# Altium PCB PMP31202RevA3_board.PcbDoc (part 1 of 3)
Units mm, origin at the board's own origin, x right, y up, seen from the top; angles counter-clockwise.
Board outline 156.21 x 130.81 mm, 4 copper layers (Top Layer, Layer 2, Layer 3, Bottom Layer), stack 1.671 mm thick; 198 components, 74 nets, 489 pads, 691 vias.
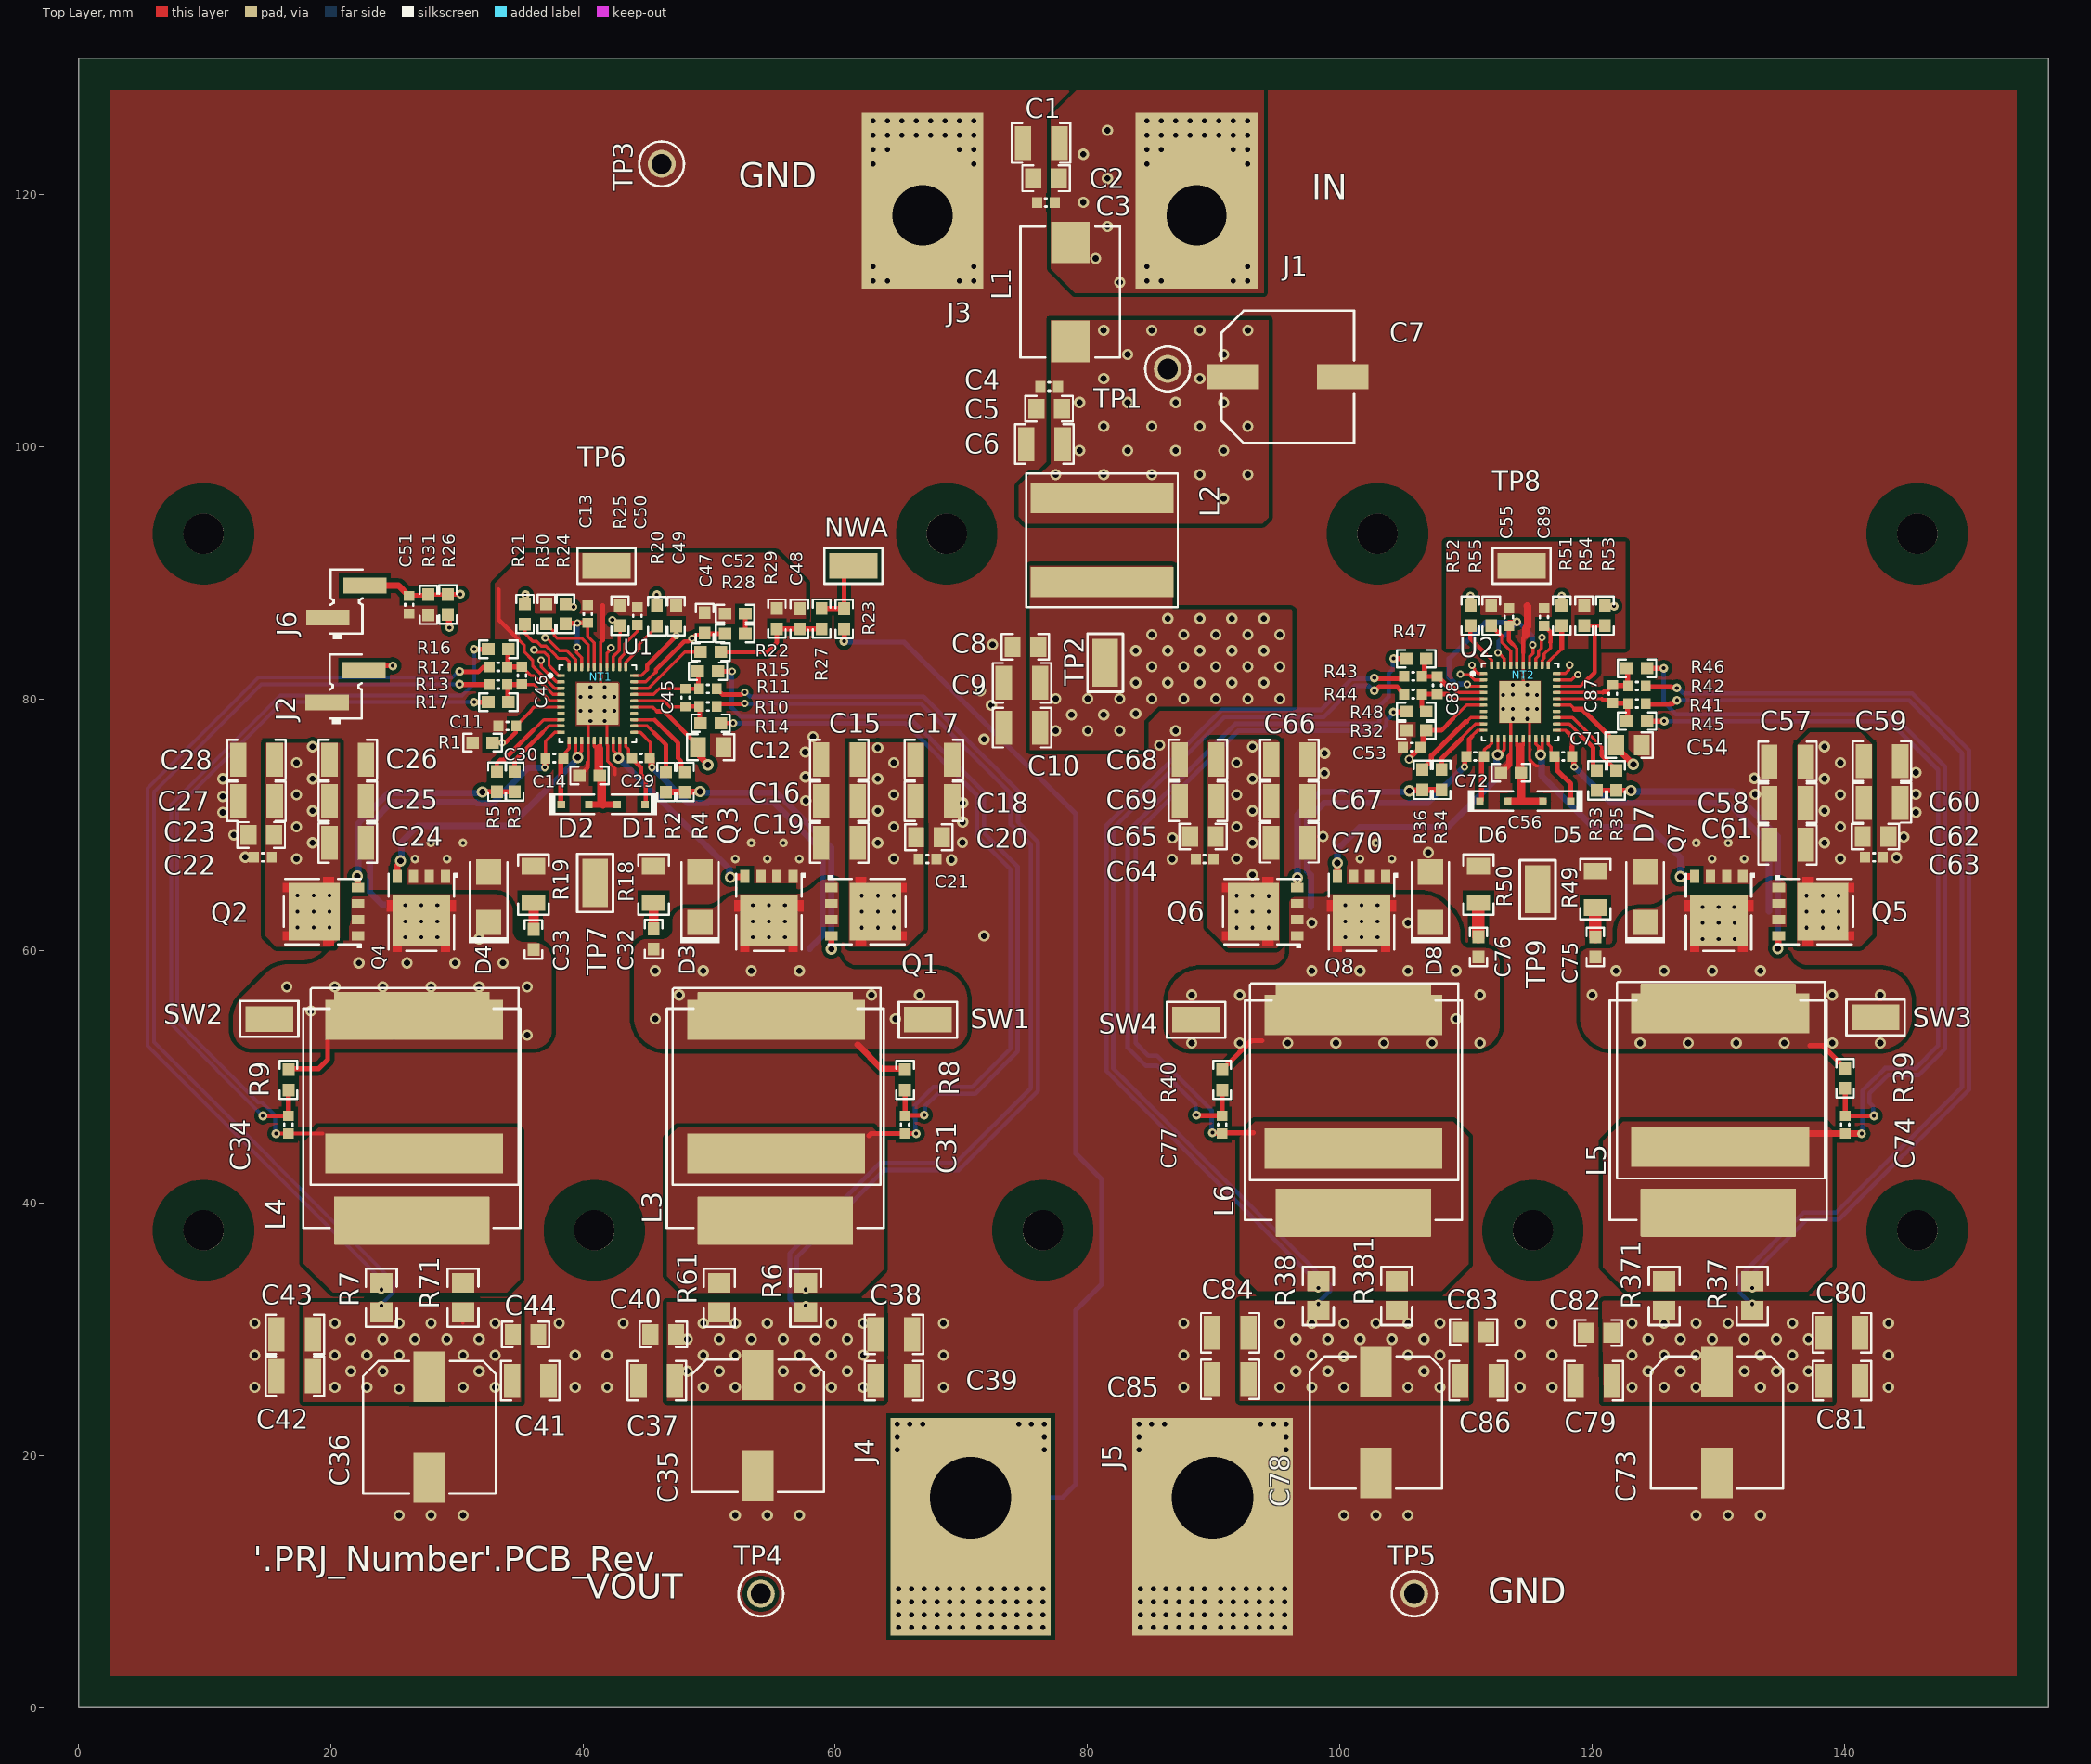
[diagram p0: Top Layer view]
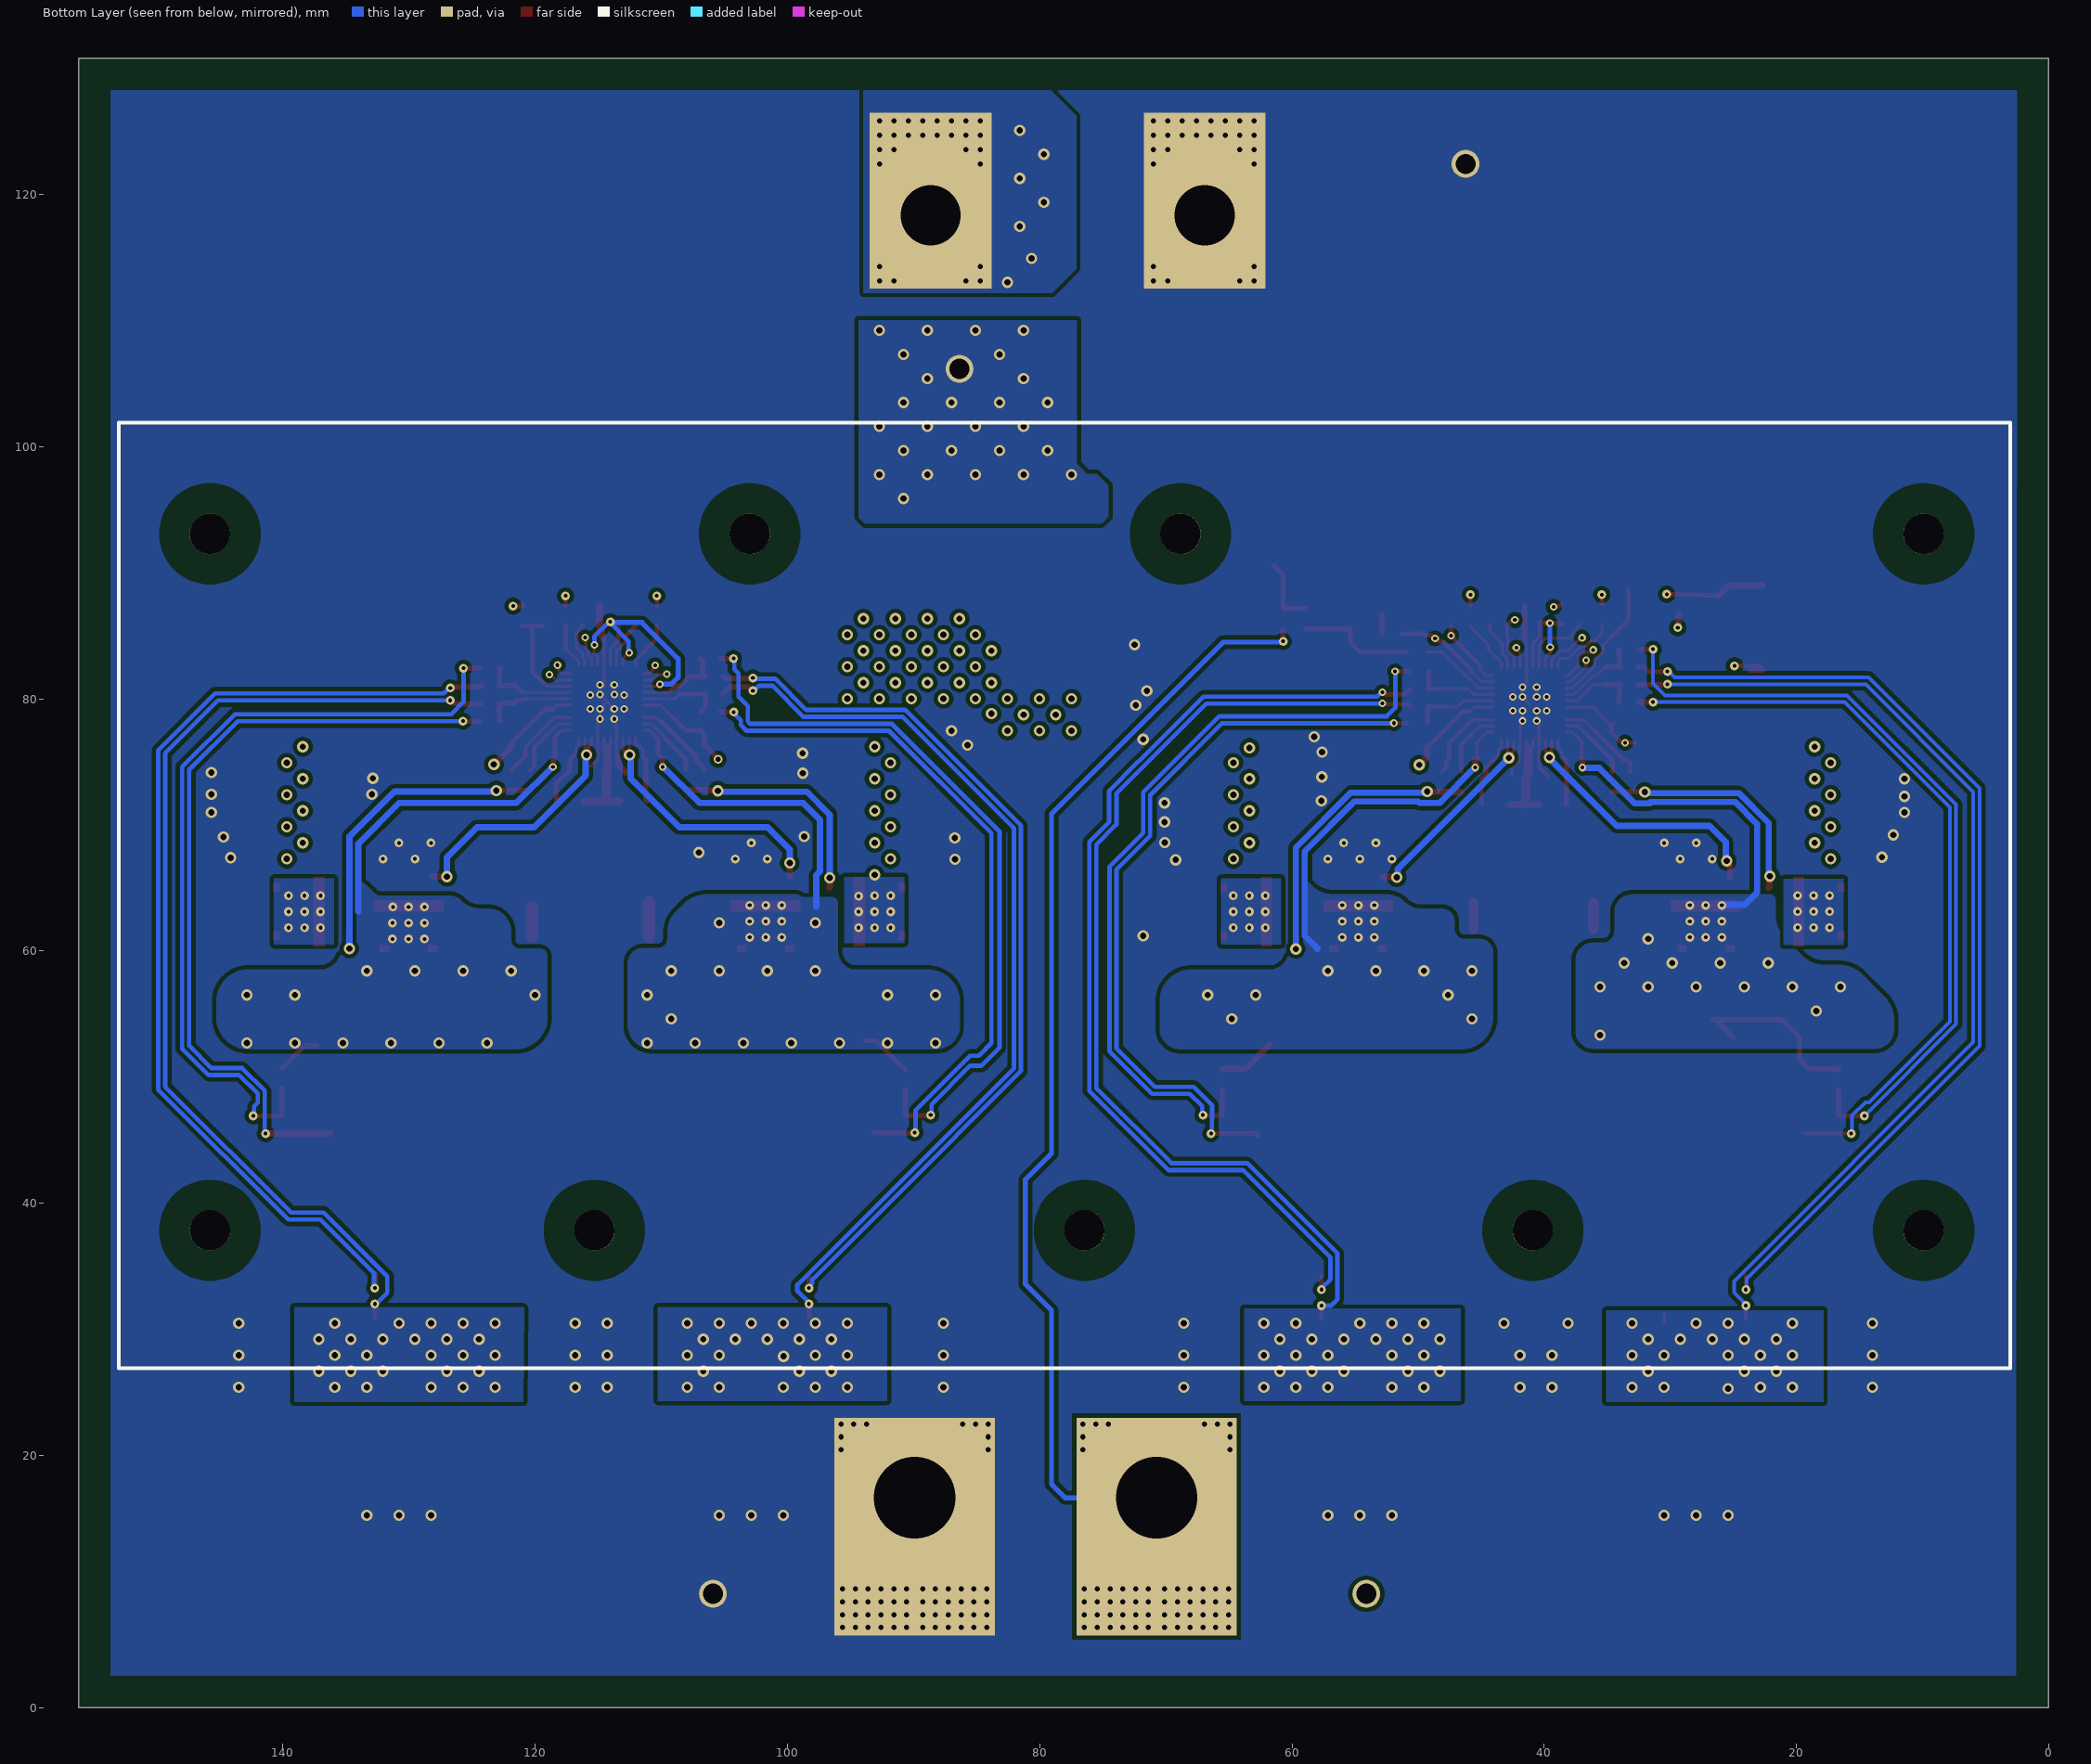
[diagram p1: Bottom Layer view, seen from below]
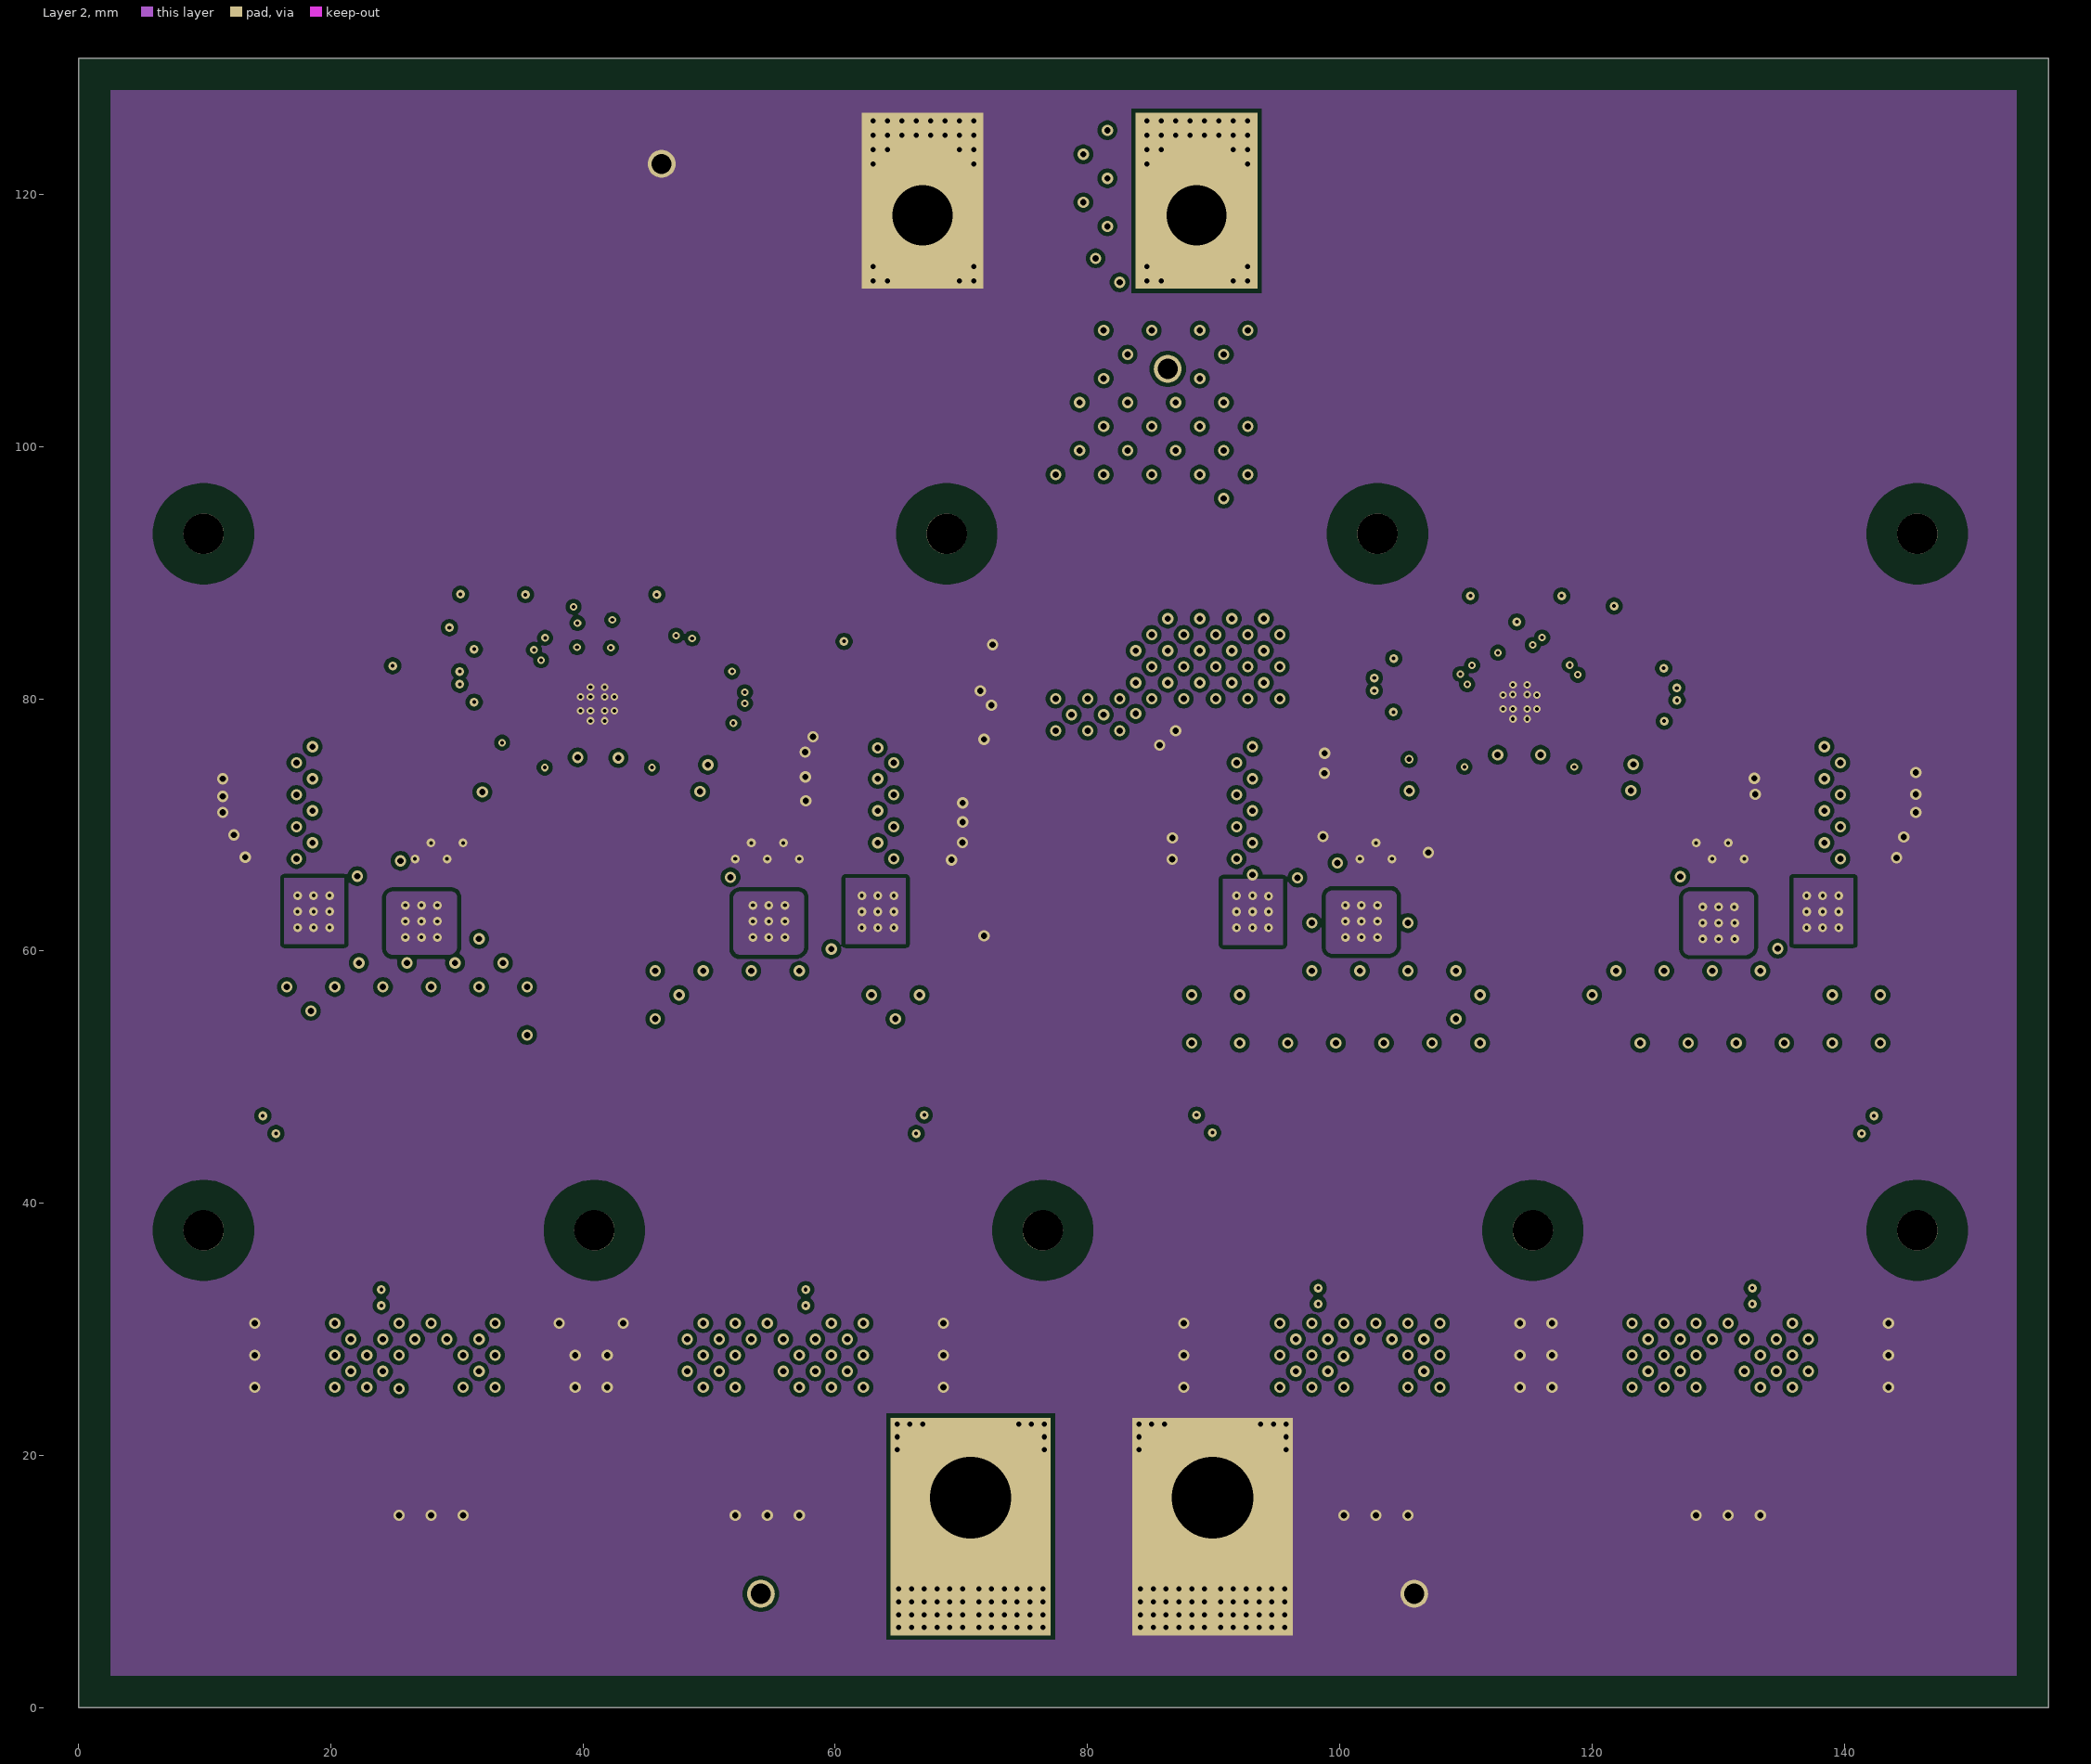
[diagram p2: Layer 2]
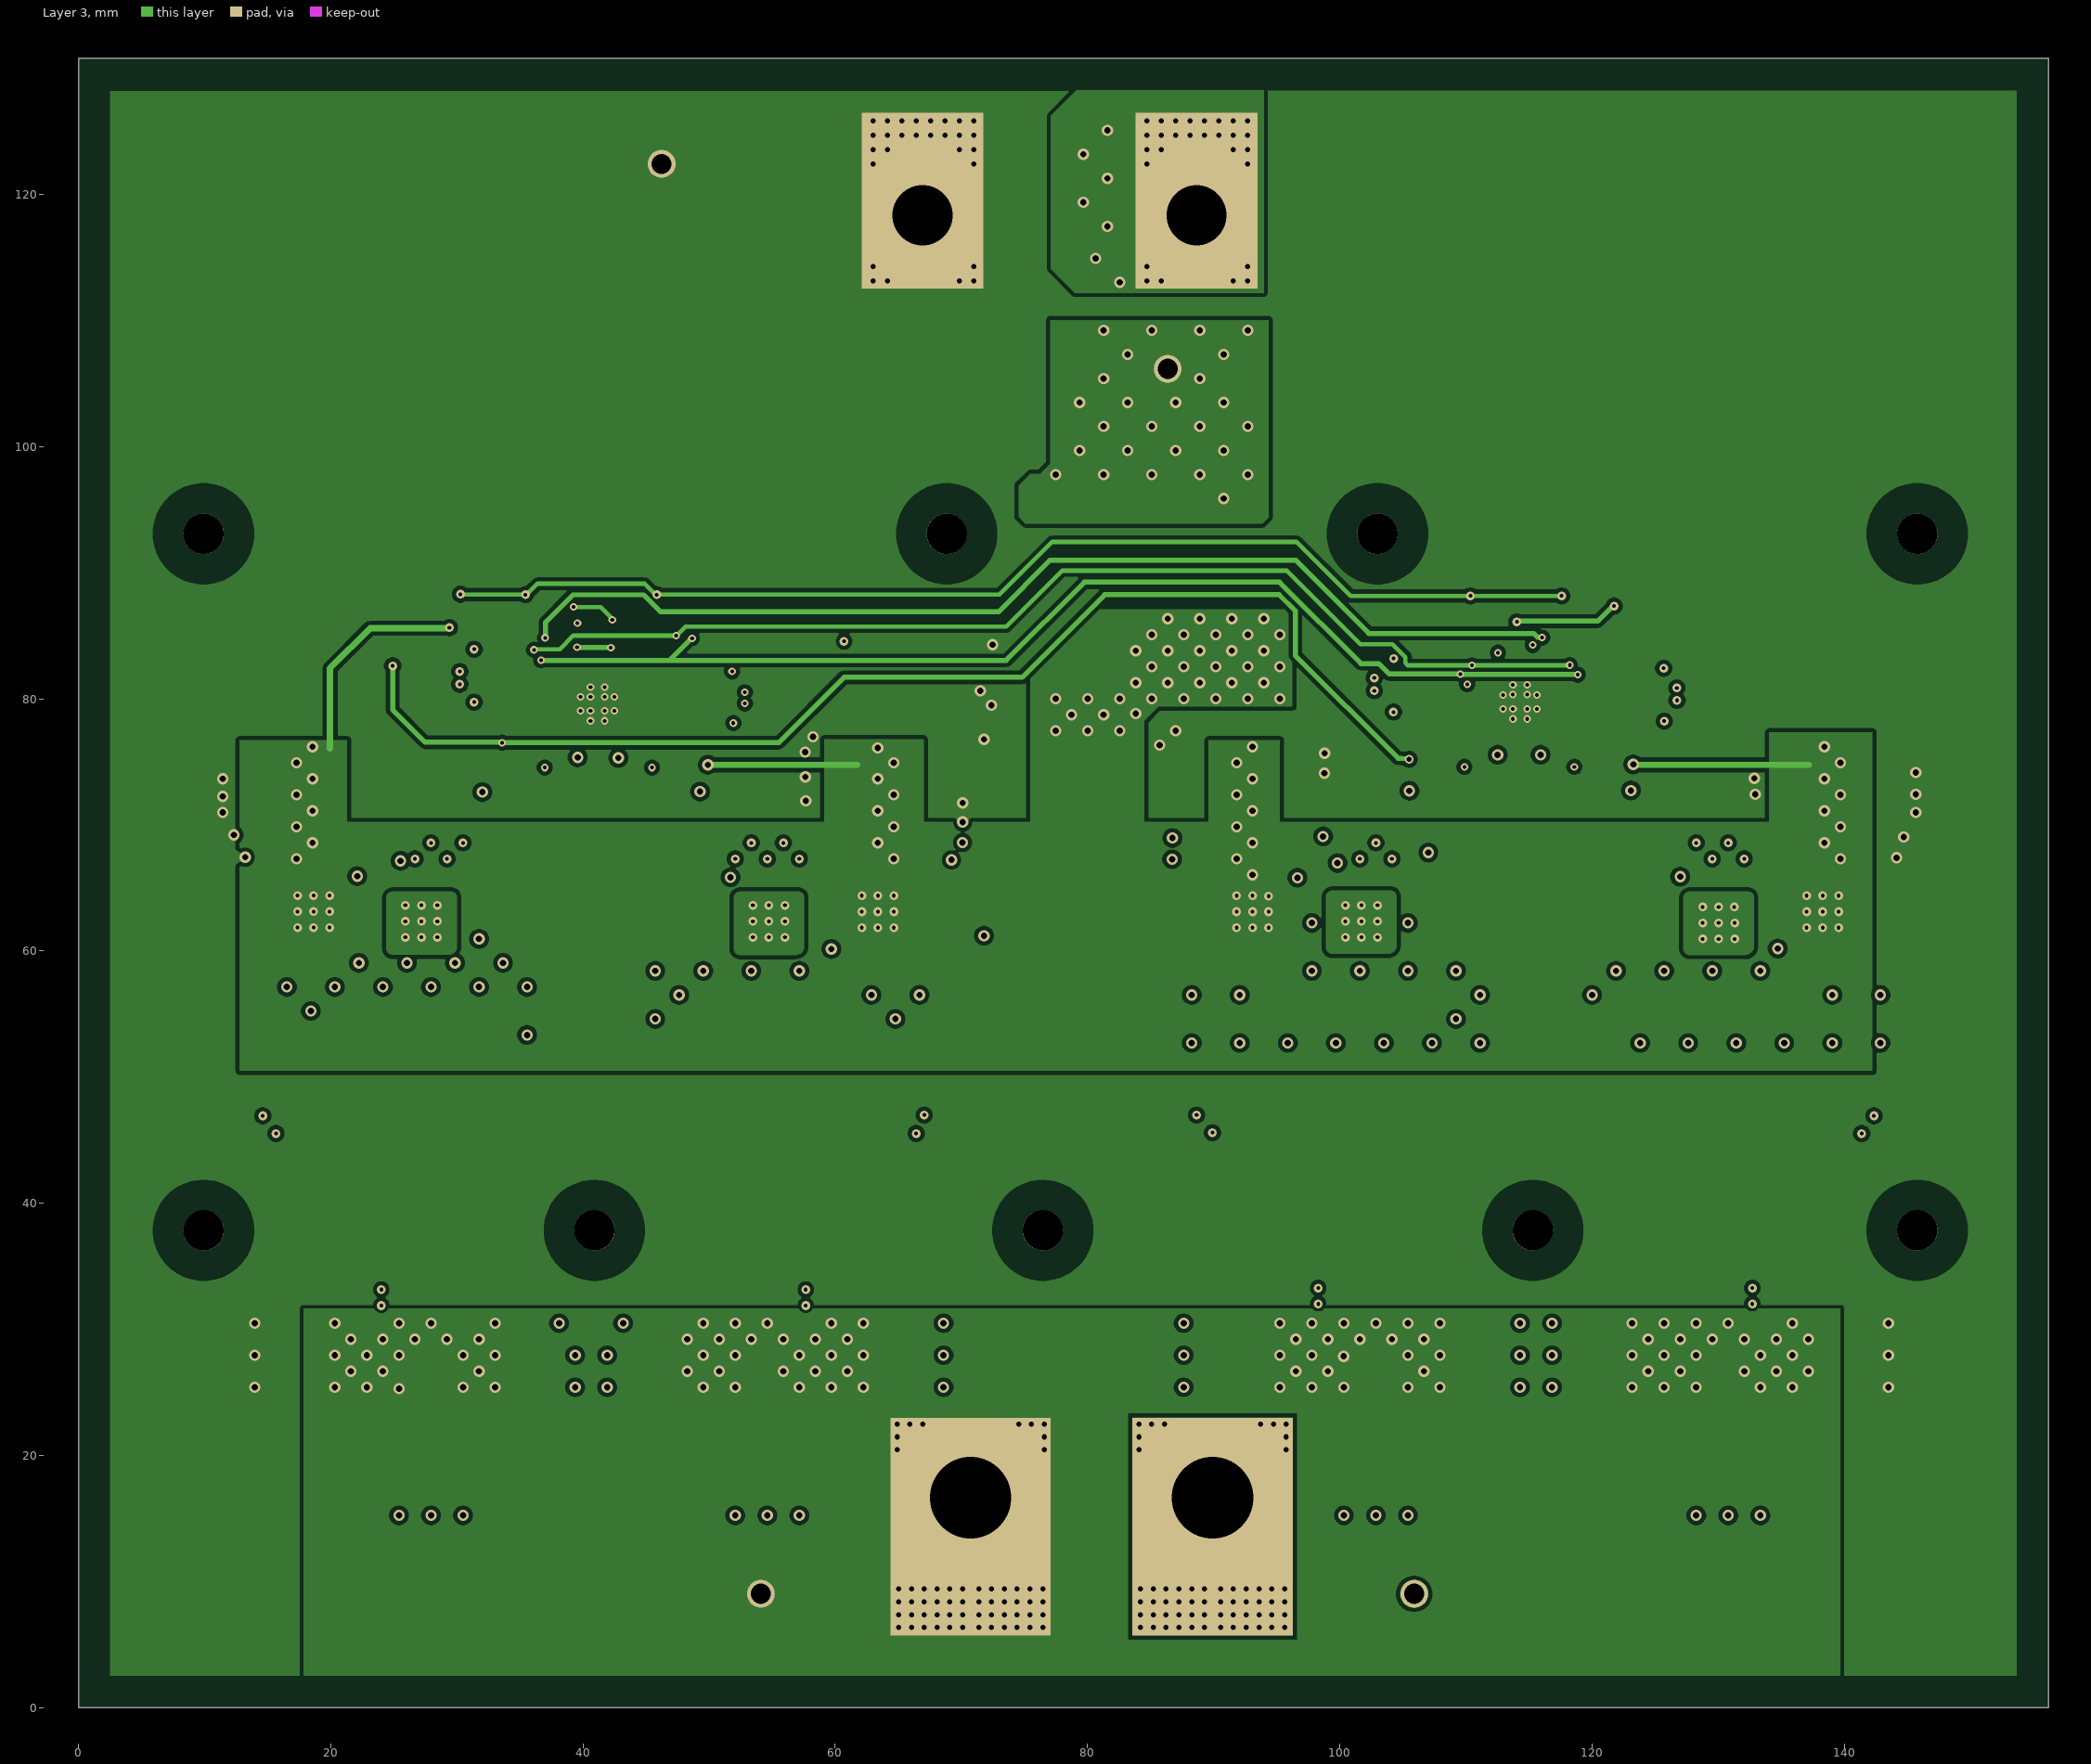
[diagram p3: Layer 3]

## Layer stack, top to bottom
Top Solder: solder mask 0.0102, Solder Resist, Dk 3.5
Top Layer: signal copper 0.0356
Dielectric 2: prepreg 0.41, PP-006, Dk 4.1
Layer 2: signal copper 0.035
Dielectric3: prepreg 0.71, FR-4, Dk 4.8
Layer 3: signal copper 0.035
Dielectric 3: prepreg 0.41, PP-006, Dk 4.1
Bottom Layer: signal copper 0.0356
Bottom Solder: solder mask 0.0102, Solder Resist, Dk 3.5

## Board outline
0,0 156.21,0 156.21,130.81 0,130.81

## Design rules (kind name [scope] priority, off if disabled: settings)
AcuteAngle [All] p1: minimum=4.50000000000000E+0001 checktracksonly=FALSE
AssemblyTestPointUsage [All] p1: valid=2
BoardOutlineClearance BoardOutlineClearance_MountingHoles [OnCopper and InComponentClass('Mounting Holes')] p1: gap=1 ignorepadtopadclearanceinfootprint=FALSE
BoardOutlineClearance BoardOutlineClearance_Poly [OnCopper and IsPoly] p2: gap=0.635 ignorepadtopadclearanceinfootprint=FALSE
BoardOutlineClearance [OnCopper and Not InComponentClass('Logo') and not InComponentClass('FiducialMark') and not InRegion(1000,500,4000,800) and not InPoly] p3: gap=1.905 ignorepadtopadclearanceinfootprint=FALSE
Clearance Clearance_Keepouts [((IsTrack Or IsArc) And Not InPoly) And IsFree and IsKeepOut vs ((IsTrack Or IsArc) And Not InPoly) And IsFree and IsKeepOut] p1: gap=0 ignorepadtopadclearanceinfootprint=FALSE
Clearance Clearance_Screws [All vs HasPad('Free-*')] p2: gap=2.4 ignorepadtopadclearanceinfootprint=TRUE
Clearance Clearance_Poly [InPolygon] p3: gap=0.32 ignorepadtopadclearanceinfootprint=TRUE
Clearance Clearance_FiducialMark [IsKeepOut and InComponentClass('FiducialMark') vs IsPad and InComponentClass('FiducialMark')] p4: gap=0 ignorepadtopadclearanceinfootprint=FALSE
Clearance [All] p5: gap=0.2 ignorepadtopadclearanceinfootprint=TRUE
ComponentClearance ComponentClearance_MountingHoles_FiducialMarks [InComponentClass('Mounting Holes') vs InComponentClass('FiducialMark')] p1: gap=1.27 collisioncheckmode=3 verticalgap=0.254 showdistances=FALSE
ComponentClearance ComponentClearance_Shunt [InComponentClass('Header') vs InComponentClass('Shunt')] p2: gap=0 collisioncheckmode=3 verticalgap=0 showdistances=FALSE
ComponentClearance ComponentClearance_Logo [InComponentClass('Logo')] p3: gap=1.27 collisioncheckmode=3 verticalgap=0.254 showdistances=FALSE
ComponentClearance ComponentClearance_ScrewToNut [(HasFootprint('NY PMS 440 0025 PH')) vs (HasFootprint('Keystone_1902C'))] p4: gap=0.127 collisioncheckmode=3 verticalgap=0.254 showdistances=FALSE
ComponentClearance ComponentClearance_MountingHoles [InComponentClass('Mounting Holes')] p5: gap=6.35 collisioncheckmode=3 verticalgap=2540 showdistances=FALSE
ComponentClearance ComponentClearance_Net_Tie [HasFootprint('Net-Tie_10mil') vs HasFootprint('RHA0040N-MFG')] p6: gap=0 collisioncheckmode=3 verticalgap=0 showdistances=FALSE
ComponentClearance ComponentClearance_SmallPassives [HasFootprint('0201*') or HasFootprint('0402*') or HasFootprint('0508') or HasFootprint('0603*') or HasFootprint('0612') or HasFootprint('0805*') or HasFootprint('0815*') or HasFootprint('0830*') or HasFootprint('1206*') or HasFootprint('1210*') or HasFootprint('1808*') or HasFootprint('1812*') or HasFootprint('1825*') or HasFootprint('2010*') or HasFootprint('2220*') or HasFootprint('2225*') or HasFootprint('2512*') or HasFootprint('2728*') or HasFootprint('3518*') vs HasFootprint('0201*') or HasFootprint('0402*') or HasFootprint('0508') or HasFootprint('0603*') or HasFootprint('0612') or HasFootprint('0805*') or HasFootprint('0815*') or HasFootprint('0830*') or HasFootprint('1206*') or HasFootprint('1210*') or HasFootprint('1808*') or HasFootprint('1812*') or HasFootprint('1825*') or HasFootprint('2010*') or HasFootprint('2220*') or HasFootprint('2225*') or HasFootprint('2512*') or HasFootprint('2728*') or HasFootprint('3518*')] p7: gap=0.38 collisioncheckmode=3 verticalgap=0.254 showdistances=FALSE
ComponentClearance ComponentClearance_THtoSMT [IsThruComponent vs IsSMTComponent] p8: gap=1.016 collisioncheckmode=3 verticalgap=0.762 showdistances=FALSE
ComponentClearance ComponentClearance_THtoTH [IsThruComponent vs IsThruComponent] p9: gap=0.762 collisioncheckmode=3 verticalgap=0.762 showdistances=FALSE
ComponentClearance [All] p10: gap=0.762 collisioncheckmode=3 verticalgap=0.254 showdistances=FALSE
DiffPairsRouting [All] p1: maxlimit=2.54 minlimit=0.254 mostfreqgap=0.254 toplayer_minwidth=0.381 toplayer_maxwidth=0.381 toplayer_prefwidth=0.381 midlayer1_minwidth=0.381 midlayer1_maxwidth=0.381 midlayer1_prefwidth=0.381 midlayer2_minwidth=0.381 midlayer2_maxwidth=0.381 midlayer2_prefwidth=0.381 bottomlayer_minwidth=0.381 bottomlayer_maxwidth=0.381 bottomlayer_prefwidth=0.381 maxuncoupledlength=25.4
FabricationTestPointUsage TestPointUsage [All] p1: valid=2 allowmultiple=FALSE
FabricationTestpoint Testpoint [All] p1: side=3 testpointundercomponent=TRUE minsize=1.016 maxsize=2.54 preferedsize=1.524 minholesize=0 maxholesize=1.016 preferedholesize=0.813 testpointgrid=0.025 allowsidetop=TRUE allowsidebottom=TRUE usegrid=TRUE gridtolerance=0
FanoutControl Fanout_LCC [IsLCC] p1: bgadir=Out bgaviamode=Centered fanoutstyle=Auto fanoutdirection=Alternating viagrid=0.025 // Fanout_LCC (Default Rule)
FanoutControl Fanout_BGA [IsBGA] p2: bgadir=Out bgaviamode=Centered fanoutstyle=Auto fanoutdirection=Alternating viagrid=0.025 // Fanout_BGA (Default Rule)
FanoutControl Fanout_Default [All] p4: bgadir=Out bgaviamode=Centered fanoutstyle=Auto fanoutdirection=Alternating viagrid=0.025 // Fanout_Default (Default Rule)
FanoutControl Fanout_Small [(CompPinCount < 5)] p5: bgadir=Out bgaviamode=Centered fanoutstyle=Auto fanoutdirection=OutThenIn viagrid=0.025 // Fanout_Small (Default Rule)
HoleSize [All] p1: absolutevalues=TRUE maxlimit=6.5 minlimit=0.3 maxpercent=80.000 minpercent=20.000
MinimumAnnularRing MinimumAnnularRing_ThermalPadVias [IsVia and InAnyComponent] p1: minimumring=0.15
MinimumAnnularRing [All] p2: minimumring=0.15
MinimumSolderMaskSliver MinimumSolderMaskSliver_Logo [InComponentClass('Logo') vs InComponentClass('Logo')] p1: minsoldermaskwidth=0.018
MinimumSolderMaskSliver [All] p2: minsoldermaskwidth=0.1
PlaneConnect [All] p1: planeconnectstyle=Relief reliefexpansion=0.254 reliefentries=4 reliefconductorwidth=0.254 reliefairgap=0.254
PolygonConnect [All] p1: connectstyle=Direct reliefconductorwidth=0.254 reliefentries=4 polygonreliefangle="90 Angle" airgapwidth=0.254
RoutingLayers [All] p1: top layer_v5=TRUE mid layer 1_v5=FALSE mid layer 2_v5=TRUE bottom layer_v5=TRUE
RoutingVias ThermalPadVias [IsVia and InAnyComponent] p1: holewidth=0.2 width=0.5 viastyle="Through Hole" minholewidth=0.2 minwidth=0.5 maxholewidth=0.5 maxwidth=0.9
RoutingVias [All] p2: holewidth=0.5 width=0.9 viastyle="Through Hole" minholewidth=0.3 minwidth=0.6 maxholewidth=1.016 maxwidth=1.651
SilkToBoardRegionClearance [Not ((IsComment or IsDesignator) And (Hide <> 'False')) and not InRegion(1000,500,4000,800)] p1:
SilkToSilkClearance SilkToSilkClearance_Pb-FreeLogo [(HasFootprint('Pb-Free_Overlay_Medium') OR HasFootprint('Pb-Free_Overlay_Small')) vs (HasFootprint('Pb-Free_Overlay_Medium') OR HasFootprint('Pb-Free_Overlay_Small'))] p1: silktosilkclearance=0
SilkToSilkClearance [All] p2: silktosilkclearance=0.1
SilkToSolderMaskClearance SilkToComponentPadClearance [(IsPad or IsFill or IsRegion) and InAnycomponent] p1: minsilkscreentomaskgap=0.127 clearancetoexposedcopper=TRUE
SilkToSolderMaskClearance "Silk to Solder Mask Opening" [All] p2: minsilkscreentomaskgap=0.1 clearancetoexposedcopper=FALSE
SolderMaskExpansion [All] p1: expansion=0.05 istentingtop=FALSE
UnRoutedNet [All] p1: checkbadconnections=TRUE
Width [All] p1: maxlimit=2.54 minlimit=0.152 preferedwidth=0.254 checkconnectedcopper=TRUE
13 further rules are at their usual default settings.

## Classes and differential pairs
component class PMP31202RevA3-SH2: !PCB1 C53 C54 C55 C56 C57 C58 C59 C60 C61 C62 C63 C64 C65 C66 C67 C68 C69 C70 C71 C72 C73 C74 C75 C76 C77 C78 C79 C80 C81 C82 C83 C84 C85 C86 C87 C88 C89 D5 D6 D7 D8 L5 L6 NT2 Q5 Q6 Q7 Q8 R32 R33 R34 R35 R36 R37 R38 R39 R40 R41 R42 R43 R44 R45 R46 R47 R48 R49 R50 R51 R52 R53 R54 R55 R371 R381 SW3 SW4 TP8 TP9 U2
component class PMP31202RevA3-SH1: C1 C2 C3 C4 C5 C6 C7 C8 C9 C10 C11 C12 C13 C14 C15 C16 C17 C18 C19 C20 C21 C22 C23 C24 C25 C26 C27 C28 C29 C30 C31 C32 C33 C34 C35 C36 C37 C38 C39 C40 C41 C42 C43 C44 C45 C46 C47 C48 C49 C50 C51 C52 D1 D2 D3 D4 J1 J2 J3 J4 J5 J6 L1 L2 L3 L4 NT1 NWA Q1 Q2 Q3 Q4 R1 R2 R3 R4 R5 R6 R7 R8 R9 R10 R11 R12 R13 R14 R15 R16 R17 R18 R19 R20 R21 R22 R23 R24 R25 R26 R27 R28 R29 R30 R31 R61 R71 SW1 SW2 TP1 TP2 TP3 TP4 TP5 TP6 TP7 U1
component class Header: J2 J6

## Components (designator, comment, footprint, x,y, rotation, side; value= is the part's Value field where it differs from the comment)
C1 "UMJ325KB7106KMHT" 1210_270 76.327,124.079 r180 top value=10uF
C2 "C0805C104K1RACTU" 0805_HV 76.708,121.285 r0 top value=0.1uF
C3 "GRM188R72A103KA01D" 0603L 76.7,119.38 r0 top value=0.01uF
C4 "GRM188R72A103KA01D" 0603L 76.962,104.775 r0 top value=0.01uF
C5 "C0805C104K1RACTU" 0805_HV 76.962,102.997 r0 top value=0.1uF
C6 "UMJ325KB7106KMHT" 1210_270 76.581,100.203 r180 top value=10uF
C7 "EEH-ZC1H101P" Panasonic_G 95.885,105.537 r0 top value=100uF
C8 "C0805C104K1RACTU" 0805_HV 75.081,84.137 r0 top value=0.1uF
C9 "UMJ325KB7106KMHT" 1210_270 74.803,81.272 r180 top value=10uF
C10 "UMJ325KB7106KMHT" 1210_270 74.803,77.716 r180 top value=10uF
C11 "GRM188R71A225KE15D" 0603L 33.998,77.852 r180 top value=2.2uF
C12 "GRM21BR71H105KA12L" 0805_HV 50.118,76.164 r0 top value=1uF
C13 "GCM188R71C474KA55D" 0603L 40.373,86.727 r270 top value=0.47uF
C14 "GRM188Z71C475KE21D" 0603 40.513,73.914 r180 top value=4.7uF
C15 "UMJ325KB7106KMHT" 1210_270 60.325,75.184 r180 top value=10uF
C16 "UMJ325KB7106KMHT" 1210_270 60.325,71.882 r180 top value=10uF
C17 "UMJ325KB7106KMHT" 1210_270 67.818,75.176 r0 top value=10uF
C18 "UMJ325KB7106KMHT" 1210_270 67.818,71.874 r0 top value=10uF
C19 "UMJ325KB7106KMHT" 1210_270 60.325,68.58 r180 top value=10uF
C20 "C0805C104K1RACTU" 0805_HV 67.427,69.025 r180 top value=0.1uF
C21 "GRM188R72A103KA01D" 0603L 67.31,67.31 r180 top value=0.01uF
C22 "GRM188R72A103KA01D" 0603L 14.605,67.429 r0 top value=0.01uF
C23 "C0805C104K1RACTU" 0805_HV 14.478,69.207 r0 top value=0.1uF
C24 "UMJ325KB7106KMHT" 1210_270 21.336,68.572 r0 top value=10uF
C25 "UMJ325KB7106KMHT" 1210_270 21.336,71.874 r0 top value=10uF
C26 "UMJ325KB7106KMHT" 1210_270 21.336,75.176 r0 top value=10uF
C27 "UMJ325KB7106KMHT" 1210_270 14.097,71.874 r180 top value=10uF
C28 "UMJ325KB7106KMHT" 1210_270 14.097,75.176 r180 top value=10uF
C29 "CGA3E2X7R1E104K080AA" 0603L 44.577,75.311 r180 top value=0.1uF
C30 "CGA3E2X7R1E104K080AA" 0603L 37.723,75.297 r0 top value=0.1uF
C31 "CGA3E2X7R1E104K080AA" 0603L 65.532,46.228 r270 top value=0.1uF
C32 "GRM188R71H102KA01D" 0603 45.593,60.96 r90 top value=1000pF
C33 "GRM188R71H102KA01D" 0603 36.068,60.922 r270 top value=1000pF
C34 "CGA3E2X7R1E104K080AA" 0603L 16.637,46.228 r270 top value=0.1uF
C35 "EEHZC1E331P" SM_RADIAL_10BMM 53.848,22.352 r270 top value=330uF
C36 "EEHZC1E331P" SM_RADIAL_10BMM 27.813,22.225 r270 top value=330uF
C37 "GRM32ER71E226KE15L" 1210_270 45.847,25.908 r180 top value=22uF
C38 "GRM32ER71E226KE15L" 1210_270 64.643,29.591 r0 top value=22uF
C39 "GRM32ER71E226KE15L" 1210_270 64.643,25.908 r0 top value=22uF
C40 "C0805C104K1RACTU" 0805_HV 46.355,29.591 r0 top value=0.1uF
C41 "C0805C104K1RACTU" 0805_HV 35.433,29.591 r180 top value=0.1uF
C42 "GRM32ER71E226KE15L" 1210_270 17.137,26.289 r180 top value=22uF
C43 "GRM32ER71E226KE15L" 1210_270 17.137,29.591 r180 top value=22uF
C44 "GRM32ER71E226KE15L" 1210_270 35.814,25.908 r0 top value=22uF
C45 "06031A330JAT2A" 0603L 48.123,80.097 r90 top value=33pF
C46 "06031A330JAT2A" 0603L 35.15,81.846 r90 top value=33pF
C47 "GRM188R71H331KA01D" 0603 49.643,86.024 r90 top value=330pF
C48 "GRM1885C1H100JA01D" 0603 57.154,86.346 r90 top value=10pF
C49 "GRM188R71C334KA01D" 0603 47.375,86.567 r90 top value=0.33uF
C50 "GRM188R71A225KE15D" 0603L 44.302,86.567 r90 top value=2.2uF
C51 "06031A330JAT2A" 0603L 26.209,87.459 r270 top value=33pF
C52 "GRM188R71E153KA01D" 0603 52.06,86.76 r180 top value=0.015uF
C53 "GRM188R71A225KE15D" 0603L 105.715,76.175 r180 top value=2.2uF
C54 "GRM21BR71H105KA12L" 0805_HV 122.936,76.327 r0 top value=1uF
C55 "GCM188R71C474KA55D" 0603L 113.411,86.487 r270 top value=0.47uF
C56 "GRM188Z71C475KE21D" 0603 113.575,74.134 r180 top value=4.7uF
C57 "UMJ325KB7106KMHT" 1210_270 135.509,75.032 r180 top value=10uF
C58 "UMJ325KB7106KMHT" 1210_270 135.509,71.73 r180 top value=10uF
C59 "UMJ325KB7106KMHT" 1210_270 143.002,75.057 r0 top value=10uF
C60 "UMJ325KB7106KMHT" 1210_270 143.002,71.755 r0 top value=10uF
C61 "UMJ325KB7106KMHT" 1210_270 135.509,68.428 r180 top value=10uF
C62 "C0805C104K1RACTU" 0805_HV 142.494,69.088 r180 top value=0.1uF
C63 "GRM188R72A103KA01D" 0603L 142.367,67.437 r180 top value=0.01uF
C64 "GRM188R72A103KA01D" 0603L 89.281,67.31 r0 top value=0.01uF
C65 "C0805C104K1RACTU" 0805_HV 89.154,69.088 r0 top value=0.1uF
C66 "UMJ325KB7106KMHT" 1210_270 96.012,75.184 r0 top value=10uF
C67 "UMJ325KB7106KMHT" 1210_270 96.012,71.874 r0 top value=10uF
C68 "UMJ325KB7106KMHT" 1210_270 88.773,75.184 r180 top value=10uF
C69 "UMJ325KB7106KMHT" 1210_270 88.773,71.882 r180 top value=10uF
C70 "UMJ325KB7106KMHT" 1210_270 96.007,68.589 r0 top value=10uF
C71 "CGA3E2X7R1E104K080AA" 0603L 117.729,75.438 r180 top value=0.1uF
C72 "CGA3E2X7R1E104K080AA" 0603L 110.744,75.438 r0 top value=0.1uF
C73 "EEHZC1E331P" SM_RADIAL_10BMM 129.921,22.606 r270 top value=330uF
C74 "CGA3E2X7R1E104K080AA" 0603L 140.081,46.228 r270 top value=0.1uF
C75 "GRM188R71H102KA01D" 0603 120.271,60.325 r90 top value=1000pF
C76 "GRM188R71H102KA01D" 0603 110.998,60.329 r270 top value=1000pF
C77 "CGA3E2X7R1E104K080AA" 0603L 90.678,46.228 r270 top value=0.1uF
C78 "EEHZC1E331P" SM_RADIAL_10BMM 102.87,22.606 r270 top value=330uF
C79 "GRM32ER71E226KE15L" 1210_270 120.142,25.908 r180 top value=22uF
C80 "GRM32ER71E226KE15L" 1210_270 139.827,29.718 r0 top value=22uF
C81 "GRM32ER71E226KE15L" 1210_270 139.827,25.908 r0 top value=22uF
C82 "C0805C104K1RACTU" 0805_HV 120.523,29.718 r0 top value=0.1uF
C83 "C0805C104K1RACTU" 0805_HV 110.617,29.773 r180 top value=0.1uF
C84 "GRM32ER71E226KE15L" 1210_270 91.313,29.718 r180 top value=22uF
C85 "GRM32ER71E226KE15L" 1210_270 91.313,26.035 r180 top value=22uF
C86 "GRM32ER71E226KE15L" 1210_270 110.998,25.908 r0 top value=22uF
C87 "06031A330JAT2A" 0603L 121.666,80.391 r90 top value=33pF
C88 "06031A330JAT2A" 0603L 107.729,81.076 r90 top value=33pF
C89 "GRM188R71A225KE15D" 0603L 116.205,86.487 r90 top value=2.2uF
D1 "PMEG6010CEJ,115" SOD-323F 43.815,71.628 r180 top value=60V
D2 "PMEG6010CEJ,115" SOD-323F 39.37,71.628 r0 top value=60V
D3 "B340A-13-F" SMA 49.276,64.262 r90 top value=40V
D4 "B340A-13-F" SMA 32.512,64.262 r90 top value=40V
D5 "PMEG6010CEJ,115" SOD-323F 117.221,71.882 r180 top value=60V
D6 "PMEG6010CEJ,115" SOD-323F 112.225,71.882 r0 top value=60V
D7 "B340A-13-F" SMA 124.206,64.262 r90 top value=40V
D8 "B340A-13-F" SMA 107.188,64.262 r90 top value=40V
J1 "CB35-36-CY" CB35-36-CY 88.646,118.364 r270 top
J2 "TSM-102-03-T-SV" Samtec_TSM-102-03-x-SV 21.169,80.993 r90 top
J3 "CB35-36-CY" CB35-36-CY 66.929,118.364 r270 top
J4 "CB70-14-CY" CB70-14-CY 70.739,16.637 r90 top
J5 "CB70-14-CY" CB70-14-CY 89.916,16.637 r90 top
J6 "TSM-102-03-T-SV" Samtec_TSM-102-03-x-SV 21.231,87.713 r90 top
L1 "PA2607.151NLT" PA2607NL 78.634,112.268 r270 top value=150nH
L2 "XAL1010-102MEB" XAL1010 81.153,92.583 r270 top value=1uH
L3 "IHLP6767GZER6R8M1A" IHLP-6767GZ-11 55.245,46.736 r90 top
L3 "XAL1510-682MEB" XAL1510 55.294,49.251 r90 top value=6.8uH
L4 "IHLP6767GZER6R8M1A" IHLP-6767GZ-11 26.416,46.736 r90 top
L4 "XAL1510-682MEB" XAL1510 26.592,49.251 r90 top value=6.8uH
L5 "IHLP6767GZER6R8M1A" IHLP-6767GZ-11 130.023,47.371 r90 top
L5 "XAL1510-682MEB" XAL1510 130.175,49.759 r90 top value=6.8uH
L6 "IHLP6767GZER6R8M1A" IHLP-6767GZ-11 101.092,47.371 r90 top
L6 "XAL1510-682MEB" XAL1510 101.092,49.632 r90 top value=6.8uH
NT1 "Net-Tie" Net-Tie_10mil 41.406,81.774 r90 top net-tie
NT2 "Net-Tie" Net-Tie_10mil 114.554,81.915 r90 top net-tie
NWA "5019" Keystone_5019 61.431,90.558 r180 top
Q1 "NVMFS5C456NL" SO-8FL 62.484,63.119 r0 top value=40V
Q2 "NVMFS5C456NL" SO-8FL 19.367,63.119 r180 top value=40V
Q3 "NVMFS5C456NL" SO-8FL 54.737,63.119 r270 top value=40V
Q4 "NVMFS5C456NL" SO-8FL 27.178,63.118 r270 top value=40V
Q5 "NVMFS5C456NL" SO-8FL 137.605,63.119 r0 top value=40V
Q6 "NVMFS5C456NL" SO-8FL 93.853,63.119 r180 top value=40V
Q7 "NVMFS5C456NL" SO-8FL 130.048,63.119 r270 top value=40V
Q8 "NVMFS5C456NL" SO-8FL 101.727,63.119 r270 top value=40V
R1 "CRCW06030000Z0EA" 0603 32.03,76.526 r0 top value=0
R2 "CRCW06034R99FKEA" 0603 46.576,73.409 r90 top value=4.99
R3 "CRCW06034R99FKEA" 0603 34.581,73.441 r270 top value=4.99
R4 "CRCW06034R99FKEA" 0603 48.088,73.409 r90 top value=4.99
R5 "CRCW06034R99FKEA" 0603 33.167,73.44 r270 top value=4.99
R6 "PE1206FRF470R007L" PE1206 57.658,32.512 r90 top value=0.007
R7 "PE1206FRF470R007L" PE1206 24.003,32.512 r270 top value=0.007
R8 "CRCW060315K0FKEA" 0603 65.532,49.784 r90 top value=15.0k
R9 "CRCW060315K0FKEA" 0603 16.637,49.784 r90 top value=15.0k
R10 "CRCW06030000Z0EA" 0603L 49.901,79.394 r0 top value=0
R11 "CRCW060349R9FKEA" 0603L 49.901,80.791 r0 top value=49.9
R12 "CRCW060349R9FKEA" 0603L 33.278,82.536 r180 top value=49.9
R13 "CRCW06030000Z0EA" 0603L 33.278,81.139 r180 top value=0
R14 "CRCW0603100RFKEA" 0603 50.118,78.064 r0 top value=100
R15 "CRCW0603100RFKEA" 0603 49.901,82.188 r0 top value=100
R16 "CRCW0603100RFKEA" 0603 33.278,83.933 r180 top value=100
R17 "CRCW0603100RFKEA" 0603 33.278,79.742 r180 top value=100
R18 "CRCW12064R70JNEAHP" 1206 45.593,65.278 r270 top value=4.7
R19 "CRCW12064R70JNEAHP" 1206 36.068,65.278 r90 top value=4.7
R20 "CRCW06030000Z0EA" 0603 45.851,86.567 r270 top value=0
R21 "CRCW06030000Z0EA" 0603 35.388,86.727 r90 top value=0
R22 "CRCW06035K49FKEA" 0603 50.117,83.712 r180 top value=5.49k
R23 "CRCW060349R9FKEA" 0603 60.706,86.346 r270 top value=49.9
R24 "CRCW06030000Z0EA" 0603 38.608,86.741 r270 top value=0
R25 "CRCW06030000Z0EA" 0603 42.93,86.6 r90 top value=0
R26 "CRCW0603221KFKEA" 0603 29.284,87.485 r270 top value=221k
R27 "CRCW0603121KFKEA" 0603 58.917,86.36 r90 top value=121k
R28 "CRCW060319K6FKEA" 0603 52.06,85.168 r180 top value=19.6k
R29 "CRCW06035K49FKEA" 0603 55.372,86.36 r270 top value=5.49k
R30 "CRCW0603110KFKEA" 0603 37.084,86.741 r270 top value=110k
R31 "CRCW060318K2FKEA" 0603 27.733,87.459 r90 top value=18.2k
R32 "CRCW06030000Z0EA" 0603 106.078,77.506 r0 top value=0
R33 "CRCW06034R99FKEA" 0603 120.396,73.533 r90 top value=4.99
R34 "CRCW06034R99FKEA" 0603 108.077,73.584 r270 top value=4.99
R35 "CRCW06034R99FKEA" 0603 121.92,73.533 r90 top value=4.99
R36 "CRCW06034R99FKEA" 0603 106.553,73.584 r270 top value=4.99
R37 "PE1206FRF470R007L" PE1206 132.715,32.639 r90 top value=0.007
R38 "PE1206FRF470R007L" PE1206 98.298,32.639 r270 top value=0.007
R39 "CRCW060315K0FKEA" 0603 140.081,49.911 r90 top value=15.0k
R40 "CRCW060315K0FKEA" 0603 90.678,49.784 r90 top value=15.0k
R41 "CRCW06030000Z0EA" 0603L 123.571,79.629 r0 top value=0
R42 "CRCW060349R9FKEA" 0603L 123.571,81.006 r0 top value=49.9
R43 "CRCW060349R9FKEA" 0603L 105.824,81.788 r180 top value=49.9
R44 "CRCW06030000Z0EA" 0603L 105.824,80.376 r180 top value=0
R45 "CRCW0603100RFKEA" 0603 123.571,78.232 r0 top value=100
R46 "CRCW0603100RFKEA" 0603 123.571,82.423 r0 top value=100
R47 "CRCW0603100RFKEA" 0603 106.078,83.185 r180 top value=100
R48 "CRCW0603100RFKEA" 0603 106.078,78.994 r180 top value=100
R49 "CRCW12064R70JNEAHP" 1206 120.271,64.897 r270 top value=4.7
R50 "CRCW12064R70JNEAHP" 1206 110.998,65.278 r90 top value=4.7
R51 "CRCW06030000Z0EA" 0603 117.602,86.614 r270 top value=0
R52 "CRCW06030000Z0EA" 0603 110.363,86.614 r90 top value=0
R53 "CRCW06030000Z0EA" 0603 121.031,86.614 r90 top value=0
R54 "CRCW06030000Z0EA" 0603 119.38,86.614 r90 top value=0
R55 "CRCW0603110KFKEA" 0603 112.014,86.614 r270 top value=110k
R61 "PE1206FRF470R007L" PE1206 50.8,32.512 r90 top value=0.007
R71 "PE1206FRF470R007L" PE1206 30.48,32.512 r270 top value=0.007
R371 "PE1206FRF470R007L" PE1206 125.73,32.639 r90 top value=0.007
R381 "PE1206FRF470R007L" PE1206 104.521,32.639 r270 top value=0.007
SW1 "5019" Keystone_5019 67.352,54.551 r180 top
SW2 "5019" Keystone_5019 15.113,54.61 r0 top
SW3 "5019" Keystone_5019 142.494,54.737 r0 top
SW4 "5019" Keystone_5019 88.618,54.551 r0 top
TP1 "5010" Keystone5010 86.36,106.172 r270 top
TP2 "5019" Keystone_5019 81.407,82.86 r270 top
TP3 "5011" Keystone5011 46.228,122.428 r90 top
TP4 "5010" Keystone5010 54.102,9.017 r0 top
TP5 "5011" Keystone5011 105.91,9.017 r0 top
TP6 "5019" Keystone_5019 41.854,90.558 r0 top
TP7 "5019" Keystone_5019 40.952,65.405 r90 top
TP8 "5019" Keystone_5019 114.427,90.551 r0 top
TP9 "5019" Keystone_5019 115.697,64.897 r90 top
U1 "LM5143QRHARQ1" RHA0040N-MFG 41.148,79.596 r0 top
U2 "LM5143QRHARQ1" RHA0040N-MFG 114.3,79.756 r0 top

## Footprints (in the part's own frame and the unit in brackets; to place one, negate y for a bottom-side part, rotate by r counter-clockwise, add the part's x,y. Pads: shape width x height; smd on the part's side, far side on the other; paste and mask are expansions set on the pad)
0603 [mm] "0603 from SM-752 data"
  rect 1x0.95 smd: 1(-0.8,0) 2(0.8,0)
  silkscreen extent -1.52,-0.69 1.52,0.69, body extent -0.87,-0.47 0.87,0.47, height 1
0603L [mm] "0603 from SM-752 data"
  rect 0.8x0.85 smd: 1(-0.7,0) 2(0.7,0)
  silkscreen extent -0.07,-0.33 0.07,0.33, body extent -0.87,-0.47 0.87,0.47, height 1
0805_HV [mil] "0805 with 30mil clearance between pads"
  rect 50x63 smd: 1(-40,0) 2(40,0)
  silkscreen extent -74,-40 74,40, body extent -43,-29 43,29, height 57
1206 [mm] "1206 from SM-752 data"
  rect 1.3x1.85 smd: 1(-1.45,0) 2(1.45,0)
  silkscreen extent -2.4,-1.21 2.4,1.21, body extent -1.7,-0.9 1.7,0.9, height 1.35
1210_270 [mm] "1210"
  rect 1.3x2.7 smd: 1(-1.45,0) 2(1.45,0)
  silkscreen extent -2.32,-1.57 2.32,1.57, body extent -1.7,-1.35 1.7,1.35, height 2.7
CB35-36-CY [mil] "Terminal 50A Lug"
  rect 550x380 hole 188 copper offset -45,0 paste-190: 1(0,0)
  body extent -960,-189 230,191, height 614
CB70-14-CY [mil] "Terminal 90A Lug"
  rect 680x500 hole 254 copper offset -90,0 paste-250: 1(0,0)
  body extent -1300,-260 250,260, height 714
IHLP-6767GZ-11 [mil] "Vishay Dale"
  rrect3% 150.5x485 smd: 1(-319.75,0) 2(319.75,0)
  silkscreen extent -343,-339 343,339, body extent -338,-338 338,338, height 272
Keystone5010 [mil] "Keystone Multipurpose loops"
  round 87 hole 63: 1(0,0)
  silkscreen extent -70,-70 70,70, body extent -63,-63 63,62, height 319
Keystone5011 [mil] "Keystone Multipurpose loops"
  round 87 hole 63: 1(0,0)
  silkscreen extent -70,-70 70,70, body extent -63,-63 63,62, height 319
Keystone_5019 [mm] "Test Point, Miniature, SMT"
  rect 3.8x2.03 smd: 1(0,0)
  silkscreen extent -2.31,-1.42 2.31,1.42, body extent -1.9,-1.02 1.9,1.02, height 2.29
Net-Tie_10mil [mil] "10mil net tie, no solder mask opening, no solder paste"
  rect 10x10 smd paste-5 mask-5: 1(-10,0) 2(10,0)
  Top Layer region: -6,5 6,5 6,-5 -6,-5
PA2607NL [mm] "SMD, 2-Leads, Body 10.31x7.65mm"
  rect 3.3x3.05 smd: 1(-3.935,0) 2(3.935,0)
  silkscreen extent -5.2,-3.95 5.2,3.95, body extent -5.44,-3.95 5.44,3.95, height 7.6
Panasonic_G [mm] "SMD, 2-Leads, Dia 10mm"
  rect 4.1x2 smd: 1(-4.35,0) 2(4.35,0)
  silkscreen extent -5.25,-5.25 5.25,5.25, body extent -5.25,-5.25 5.25,5.25, height 10.51
PE1206 [mm] "YAGEO"
  rect 1.57x1.78 smd: 1(-1.165,0) 2(1.165,0)
  silkscreen extent -2.3,-1.22 2.3,1.22, body extent -1.72,-0.92 1.72,0.92, height 0.89
RHA0040N-MFG [mm]
  rrect40% 0.6x0.25 smd paste+0 mask+0: 1(-2.9,2.25) 2(-2.9,1.75) 3(-2.9,1.25) 4(-2.9,0.75) 5(-2.9,0.25) 6(-2.9,-0.25) 7(-2.9,-0.75) 8(-2.9,-1.25) 9(-2.9,-1.75) 10(-2.9,-2.25) 21(2.9,-2.25) 22(2.9,-1.75) 23(2.9,-1.25) 24(2.9,-0.75) 25(2.9,-0.25) 26(2.9,0.25) 27(2.9,0.75) 28(2.9,1.25) 29(2.9,1.75) 30(2.9,2.25)
  rrect40% 0.25x0.6 smd paste+0 mask+0: 11(-2.25,-2.9) 12(-1.75,-2.9) 13(-1.25,-2.9) 14(-0.75,-2.9) 15(-0.25,-2.9) 16(0.25,-2.9) 17(0.75,-2.9) 18(1.25,-2.9) 19(1.75,-2.9) 20(2.25,-2.9) 31(2.25,2.9) 32(1.75,2.9) 33(1.25,2.9) 34(0.75,2.9) 35(0.25,2.9) 36(-0.25,2.9) 37(-0.75,2.9) 38(-1.25,2.9) 39(-1.75,2.9) 40(-2.25,2.9)
  rrect3% 3.3x3.3 smd paste-1000 mask+0: 41(0,0)
  silkscreen extent -3.87,-3.05 3.05,3.05, body extent -3.3,-3.3 3.3,3.3, height 0.25
Samtec_TSM-102-03-x-SV [mm] "Header, 2.54mm, 2x1, SMT"
  rect 1.27x3.43 smd: 1(-1.27,1.46) 2(1.27,-1.46)
  silkscreen extent -3,-1.27 2.54,1.27, body extent -2.54,-2.6 2.54,2.6, height 14.48
SM_RADIAL_10BMM [mm] "Nichicon 10x10"
  rect 4x2.5 smd: 1(-4,0) 2(4,0)
  silkscreen extent -5.25,-5.25 5.25,5.25, body extent -5.25,-5.25 5.25,5.25, height 10.5
SMA [mm] "Molded Diode, 2-Leads, Body 4.3x2.6mm, IPC Medium Density, based on OnSemi component dimensions and land pattern"
  rect 2x2 smd: 1(-2,0) 2(2,0)
  silkscreen extent -3.66,-1.57 2.79,1.57, body extent -2.6,-1.3 2.6,1.3, height 2.42
SO-8FL [mm] "ON SEMICONDUCTOR, DFN5 5x6, 1.27P, CASE 488AA"
  rect 1x0.75 smd: 1(-2.795,1.905) 2(-2.795,0.635) 3(-2.795,-0.635) 4(-2.795,-1.905)
  rect 4.055x4.56 smd: 5(0.698,0)
  Top Layer region: 3.2,-2.28 3.2,-1.53 2.65,-1.53 2.65,-2.28
  Top Layer region: 3.2,1.53 3.2,2.28 2.655,2.28 2.655,1.53
  Top Layer region: 0,-2.775 0,2.775 -0.905,2.775 -0.905,-2.775
  silkscreen extent -3.1,-2.6 3.1,2.9, body extent -3.17,-2.67 3.17,2.67, height 1.11
SOD-323F [mm] "NXP recommended land pattern"
  rect 0.6x0.6 smd paste-0.05: 1(-1.1,0) 2(1.1,0)
  silkscreen extent -2.06,-0.86 1.53,0.86, body extent -1.35,-0.67 1.35,0.68, height 0.79
XAL1010 [mm] "COILCRAFT"
  rect 2.38x11.31 smd: 1(-3.325,0) 2(3.325,0)
  silkscreen extent -5.3,-6 5.3,6, body extent -5.25,-5.9 5.25,5.9, height 10
XAL1510 [mm] "COILCRAFT"
  rect 3.18x14.1 smd: 1(-5.3,0) 2(5.3,0)
  silkscreen extent -7.8,-8.3 7.8,8.2, body extent -7.7,-8.2 7.7,8.2, height 11

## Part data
C1 C6 C9 C10 C15 C16 C17 C18 C19 C24 C25 C26 C27 C28 C57 C58 C59 C60 C61 C66 C67 C68 C69 C70: library part GRM32ER71J106KA12L, "CAP, CERM, 10 µF, 63 V,+/- 10%, X7R, 1210", Cap_Case=1210, Manufacturer="Taiyo Yuden", Supplier Part Number 1=587-4279-1-ND, TempCo=X7R, Tolerance_%=10%, Value1=Unknown, Value2=50V, ValueDisplayed=10uF
C2 C5 C8 C20 C23 C40 C41 C62 C65 C82 C83: library part CMP-0007722-2, "CAP, CERM, 0.1 uF, 100 V, +/- 10%, X7R, 0805", Cap_Case=0805, Manufacturer=Kemet, Supplier Part Number 1=399-3486-1-ND, TempCo=X7R, Tolerance_%=10%, Value1="0.064 ohm", Value2=100V, ValueDisplayed=0.1uF
C3 C4 C21 C22 C63 C64: library part CMP-0007468-5, "CAP, CERM, 0.01 uF, 100 V, +/- 10%, X7R, 0603", Cap_Case=0603, Manufacturer=MuRata, Supplier Part Number 1=GRM188R72A103KA01D-ND, TempCo=X7R, Tolerance_%=10%, Value1=Unknown, Value2=100V, ValueDisplayed=0.01uF
C7: library part EEHZC1J560P, "CAP, Polymer Hybrid, 56 µF, 63 V,+/- 20%, 30 ohm, 10x10 SMD", Cap_Case=10x10.2mm, Manufacturer=Panasonic, Supplier Part Number 1=P15462CT-ND, Tolerance_%=20, Value1="0.028 ohm", Value2=50V, ValueDisplayed=100µF
C11 C50 C53 C89: library part CMP-0007370-4, "CAP, CERM, 2.2 uF, 10 V, +/- 10%, X7R, 0603", Cap_Case=0603, Manufacturer=MuRata, Supplier Part Number 1=490-4520-1-ND, TempCo=X7R, Tolerance_%=10%, Value1="0.009 ohm", Value2=10V, ValueDisplayed=2.2uF
C12 C54: library part GRM21BR72A474KA73L, "CAP, CERM, 0.47 µF, 100 V,+/- 10%, X7R, 0805", Cap_Case=0805, Manufacturer=MuRata, Supplier Part Number 1=490-4736-1-ND, TempCo=X7R, Tolerance_%=10, Value2=50V, ValueDisplayed=1µF
C13 C55: library part CMP-0007138-4, "CAP, CERM, 0.47 uF, 16 V, +/- 10%, X7R, AEC-Q200 Grade 1, 0603", Cap_Case=0603, Manufacturer=MuRata, Supplier Part Number 1=490-4775-1-ND, TempCo=X7R, Tolerance_%=10%, Value1=Unknown, Value2=16V, ValueDisplayed=0.47uF
C14 C56: "CAP, CERM, 4.7 µF, 16 V,+/- 10%, X7R, 0603", Cap_Case=0603, Manufacturer=MuRata, TempCo=X7R, Tolerance_%=10, Value2=16V, ValueDisplayed=4.7µF
C29 C30 C31 C34 C71 C72 C74 C77: library part CMP-0007077-5, "CAP, CERM, 0.1 uF, 25 V, +/- 10%, X7R, AEC-Q200 Grade 1, 0603", Cap_Case=0603, Manufacturer=TDK, Supplier Part Number 1=445-5667-1-ND, TempCo=X7R, Tolerance_%=10%, Value1=Unknown, Value2=25V, ValueDisplayed=0.1uF
C32 C33 C75 C76: library part GRM188R72A102KA01D, "CAP, CERM, 1000 pF, 100 V,+/- 10%, X7R, 0603", Cap_Case=0603, Manufacturer=MuRata, Supplier Part Number 1=490-1494-1-ND, TempCo=X7R, Tolerance_%=10, Value2=50V, ValueDisplayed=1000pF
C35 C36 C73 C78: "CAP, Polymer Hybrid, 330 µF, 25 V,+/- 20%, 20 ohm, 10x10 SMD", Manufacturer=Panasonic, Supplier Part Number 1=P15459CT-ND, Tolerance_%=20, Value1="20 ohm", Value2=25V, ValueDisplayed=330µF
C37 C38 C39 C42 C43 C44 C79 C80 C81 C84 C85 C86: "CAP, CERM, 22 µF, 25 V,+/- 10%, X7R, 1210", Cap_Case=1210, Manufacturer=MuRata, Supplier Part Number 1=490-5313-1-ND, TempCo=X7R, Tolerance_%=10, Value1="0.002334 ohm", Value2=25V, ValueDisplayed=22µF
C45 C46 C51 C87 C88: library part CMP-0006722-4, "CAP, CERM, 33 pF, 100 V, +/- 5%, C0G/NP0, 0603", Cap_Case=0603, Manufacturer=AVX, Supplier Part Number 1=478-1143-1-ND, TempCo=C0G/NP0, Tolerance_%=5%, Value1="0.209 ohm", Value2=100V, ValueDisplayed=33pF
C47: library part GRM188R71H221KA01D, "CAP, CERM, 220 pF, 50 V,+/- 10%, X7R, 0603", Cap_Case=0603, Manufacturer=MuRata, Supplier Part Number 1=490-1486-1-ND, TempCo=X7R, Tolerance_%=10, Value2=50V, ValueDisplayed=330pF
C48: library part 06035A6R8CAT2A, "CAP, CERM, 6.8 pF, 50 V,+/- 4%, C0G/NP0, 0603", Cap_Case=0603, Manufacturer=MuRata, Supplier Part Number 1=490-1403-1-ND, TempCo=C0G/NP0, Tolerance_%=5, Value2=50V, ValueDisplayed=10pF
C49: "CAP, CERM, 0.33 µF, 16 V,+/- 10%, X7R, 0603", Cap_Case=0603, Manufacturer=MuRata, Supplier Part Number 1=490-3294-1-ND, TempCo=X7R, Tolerance_%=10, Value2=16V, ValueDisplayed=0.33µF
C52: library part GRM188R71C473KA01D, "CAP, CERM, 0.047 µF, 16 V,+/- 10%, X7R, 0603", Cap_Case=0603, Manufacturer=MuRata, Supplier Part Number 1=81-GRM39X153K25D, TempCo=X7R, Tolerance_%=10, Value2=25V, ValueDisplayed=0.015µF
D1 D2 D5 D6: library part CMP-0077011-2, "Diode, Schottky, 60 V, 1 A, SOD-323F", Manufacturer=Nexperia, Value1=1A, Value2=0.66V
D3 D4 D7 D8: library part B360A-13-F, "Diode, Schottky, 60 V, 3 A, SMA", Manufacturer="Diodes Inc.", Supplier Part Number 1=B340A-FDICT-ND, Value1=3A, Value2=0.5V
J1 J3: "Terminal 50A Lug", Current_A=50A, Manufacturer=Panduit, Supplier Part Number 1=CB35-36-CY-ND, Voltage_V=600
J2 J6: "Header, 2.54mm, 2x1, Tin, SMT", Color=Black, Current_A=5.4, Manufacturer=Samtec, Voltage_V=475
J4 J5: "Terminal 90A Lug", Current_A=90A, Manufacturer=Panduit, Supplier Part Number 1=CB70-14-CY-ND, Voltage_V=600
L1: "Inductor, Ferrite Bead, Ferrite, 150 nH, 41 A, 0.00029 ohm, SMD", Manufacturer="Pulse Engineering", Supplier Part Number 1=553-2160-1-ND, Value1="0.00029 ohm", Value2=41A, ValueDisplayed=150nH
L2: "Inductor, Shielded, Composite, 1 µH, 43.5 A, 0.001 ohm, SMD", Manufacturer=Coilcraft, Supplier Part Number 1=994-XAL1010-102MEB, Value1="0.001 ohm", Value2=43.5A, ValueDisplayed=1µH
L3 L4 L5 L6: library part CMP-0063534-2, "Inductor, Shielded, Powdered Iron, 6.8 uH, 18.5 A, 0.00615 ohm, SMD"
L3 L4 L5 L6: library part CMP-0060971-1, "Inductor, Shielded, Composite, 6.8 uH, 26 A, 0.00417 ohm, SMD", Manufacturer=Coilcraft, Value1="0.00417 ohm", Value2=26A, ValueDisplayed=6.8uH
NT1 NT2: library part CMP-0078142-3, "Single point connection between nets.", Manufacturer=N/A
NWA SW1 SW2 SW3 SW4 TP2 TP6 TP7 TP8 TP9: library part CMP-0055162-1, "Test Point, Miniature, SMT", Manufacturer=Keystone, Supplier Part Number 1=36-5019TR-ND
Q1 Q2 Q3 Q4 Q5 Q6 Q7 Q8: library part NVMFS5C682NLT1G, "MOSFET, N-CH, 60 V, 40 A, AEC-Q101, SO-8FL", Alternate Manufacturer=None, Manufacturer="ON Semiconductor", Value1="0.0037 ohm", Value2="18 nC"
R1 R20 R21 R24 R25 R32 R51 R52 R53 R54: "RES, 0, 5%, 0.1 W, 0603", Manufacturer=Vishay-Dale, Power_W=0.1, Supplier Part Number 1=541-0.0GCT-ND, TempCo="200 ppm/C", Tolerance_%=5, Value1=5%, Value2=0.1W, Value_Code=0000, ValueDisplayed=0
R2 R3 R4 R5 R33 R34 R35 R36: library part CRCW06034R75FKEA, "RES, 4.75, 1%, 0.1 W, 0603", Manufacturer=Vishay-Dale, Power_W=0.1, Supplier Part Number 1=541-4.99HHCT-ND, TempCo="100 ppm/C", Tolerance_%=1, Value1=1%, Value2=0.1W, Value_Code=4R99, ValueDisplayed=4.99
R6 R7 R37 R38 R61 R71 R371 R381: "RES, 0.007, 1%, 1 W, AEC-Q200 Grade 0, 1206", Manufacturer="Yageo America", Power_W=1, Supplier Part Number 1=PE1206FRF470R007L-ND, TempCo="100 ppm/C", Value1=1%, Value2=1W, Value_Code=7L000, ValueDisplayed=0.007
R8 R9 R39 R40: "RES, 15.0 k, 1%, 0.1 W, 0603", Manufacturer=Vishay-Dale, Power_W=0.1, Supplier Part Number 1=541-15.0KHCT-ND, TempCo="100 ppm/C", Tolerance_%=1, Value1=1%, Value2=0.1W, Value_Code=15k0, ValueDisplayed=15.0k
R10 R13 R41 R44: library part CMP-0025697-4, "RES, 0, 5%, 0.1 W, AEC-Q200 Grade 0, 0603", Manufacturer=Vishay-Dale, Power_W=100mW, Supplier Part Number 1=541-0.0GCT-ND, TempCo="200 ppm/C", Tolerance_%=5%, Value2=0.1W, Value_Code=0000, ValueDisplayed=0
R11 R12 R42 R43: library part CMP-0022448-4, "RES, 49.9, 1%, 0.1 W, AEC-Q200 Grade 0, 0603", Manufacturer=Vishay-Dale, Power_W=100mW, Supplier Part Number 1=541-49.9HCT-ND, TempCo="100 ppm/C", Tolerance_%=1%, Value2=0.1W, Value_Code=49R9, ValueDisplayed=49.9
R14 R15 R16 R17 R45 R46 R47 R48: "RES, 100, 1%, 0.1 W, 0603", Manufacturer=Vishay-Dale, Power_W=0.1, Supplier Part Number 1=541-100HCT-ND, TempCo="100 ppm/C", Tolerance_%=1, Value1=1%, Value2=0.1W, Value_Code=100R, ValueDisplayed=100
R18 R19 R49 R50: "RES, 4.7, 5%, 0.75 W, AEC-Q200 Grade 0, 1206", Manufacturer=Vishay-Dale, Power_W=0.75, Supplier Part Number 1=541-4.7UACT-ND, TempCo="200 ppm/C", Tolerance_%=5, Value1=5%, Value2=0.75W, Value_Code=4R70, ValueDisplayed=4.7
R22 R29: "RES, 5.49 k, 1%, 0.1 W, 0603", Manufacturer=Vishay-Dale, Power_W=0.1, Supplier Part Number 1=541-5.49KHCT-ND, TempCo="100 ppm/C", Tolerance_%=1, Value1=1%, Value2=0.1W, Value_Code=5k49, ValueDisplayed=5.49k
R23: "RES, 49.9, 1%, 0.1 W, 0603", Manufacturer=Vishay-Dale, Power_W=0.1, Supplier Part Number 1=541-49.9HCT-ND, TempCo="100 ppm/C", Tolerance_%=1, Value1=1%, Value2=0.1W, Value_Code=49R9, ValueDisplayed=49.9
R26: "RES, 221 k, 1%, 0.1 W, 0603", Manufacturer=Vishay-Dale, Power_W=0.1, Supplier Part Number 1=541-221KHCT-ND, TempCo="100 ppm/C", Tolerance_%=1, Value1=1%, Value2=0.1W, Value_Code=221k
R27: "RES, 121 k, 1%, 0.1 W, 0603", Manufacturer=Vishay-Dale, Power_W=0.1, Supplier Part Number 1=541-121KHCT-ND, TempCo="100 ppm/C", Tolerance_%=1, Value1=1%, Value2=0.1W, Value_Code=121k
R28: library part CRCW060333K2FKEA, "RES, 33.2 k, 1%, 0.1 W, 0603", Manufacturer=Vishay-Dale, Power_W=0.1, Supplier Part Number 1=541-19.6KHCT-ND, TempCo="100 ppm/C", Tolerance_%=1, Value1=1%, Value2=0.1W, Value_Code=19k6, ValueDisplayed=19.6k
R30 R55: "RES, 110 k, 1%, 0.1 W, 0603", Manufacturer=Vishay-Dale, Power_W=0.1, Supplier Part Number 1=541-110KHCT-ND, TempCo="100 ppm/C", Tolerance_%=1, Value1=1%, Value2=0.1W, Value_Code=110k
R31: "RES, 18.2 k, 1%, 0.1 W, 0603", Manufacturer=Vishay-Dale, Power_W=0.1, Supplier Part Number 1=541-18.2KHCT-ND, TempCo="100 ppm/C", Tolerance_%=1, Value1=1%, Value2=0.1W, Value_Code=18k2, ValueDisplayed=18.2k
TP1 TP4: library part CMP-0055147-2, "Test Point, Multipurpose, Red, TH", Color=Red, Manufacturer="Keystone Electronics", Supplier Part Number 1=36-5010-ND
TP3 TP5: library part CMP-0055148-2, "Test Point, Multipurpose, Black, TH", Color=Black, Manufacturer="Keystone Electronics", Supplier Part Number 1=36-5011-ND
U1 U2: library part CMP-0094639-1, "Automotive 3.5-V to 65-V Dual Synchronous Buck Controller With Low IQ", Manufacturer="Texas Instruments", Max Supply Voltage=65V, Min Supply Voltage=3.5V, Nominal Supply Current=15-25uA, Operating Temperature Range="-40°C to +150°C", Output Voltage=0.6-55V, Switching Frequency=0.1-2.2MHz

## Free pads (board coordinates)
  round 3.2 hole 3.2 unplated: 9(9.906,37.846) 9(9.906,93.091) 9(40.894,37.846) 9(68.834,93.091) 9(76.454,37.846) 9(102.997,93.091) 9(115.316,37.846) 9(145.796,37.846) 9(145.796,93.091)

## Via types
v1: diameter 0.9, hole 0.5, Top Layer to Bottom Layer, tented bottom, 173 vias
v2: diameter 0.813, hole 0.406, Top Layer to Bottom Layer, 172 vias
v3: diameter 0.9, hole 0.5, Top Layer to Bottom Layer, 82 vias
v4: diameter 0.9, hole 0.5, Top Layer to Bottom Layer, tented both sides, 73 vias
v5: diameter 0.7, hole 0.3, Top Layer to Bottom Layer, 69 vias
v6: diameter 0.7, hole 0.3, Top Layer to Bottom Layer, tented bottom, 28 vias
v7: diameter 0.6, hole 0.3, Top Layer to Bottom Layer, tented both sides, 26 vias
v8: diameter 0.7, hole 0.3, Top Layer to Bottom Layer, tented both sides, 24 vias
v9: diameter 0.6, hole 0.3, Top Layer to Bottom Layer, 24 vias
v10: diameter 0.9, hole 0.5, Top Layer to Bottom Layer, tented top, 13 vias
v11: diameter 0.7/0.7/0.7/0.7 (per signal layer), hole 0.3, Top Layer to Bottom Layer, tented bottom, 2 vias
v12: diameter 0.7/0.7/0.7/0.7 (per signal layer), hole 0.3, Top Layer to Bottom Layer, tented both sides, 2 vias
v13: diameter 0.7, hole 0.3, Top Layer to Bottom Layer, tented top, 1 vias
v14: diameter 0.7, hole 0.4, Top Layer to Bottom Layer, tented both sides, 1 vias
v15: diameter 0.6, hole 0.3, Top Layer to Bottom Layer, tented top, 1 vias

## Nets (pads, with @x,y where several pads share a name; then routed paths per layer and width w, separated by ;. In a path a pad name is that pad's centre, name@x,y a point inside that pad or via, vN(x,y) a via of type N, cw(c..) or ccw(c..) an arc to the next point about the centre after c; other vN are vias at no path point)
5Vext: C11.1 C53.1 J2.2 R1.2 R32.2 U1.6 U2.6 | length 130.6
  Top Layer w0.25: C11.1@34.698,77.852 34.698,77.877 35.875,79.054 35.875,79.119 36.102,79.346 U1.6@38.248,79.346 ; 108.977,78.41 110.073,79.506 U2.6@111.4,79.506
  Top Layer w0.35: J2.2@22.629,82.263 J2.2@23.709,82.263 ; R1.2@32.83,76.526 v7(33.58,76.526) 33.862,76.526 34.663,77.327 34.663,77.816 C11.1@34.698,77.852 C11.1@34.473,78.077 ; R32.2@106.878,77.506 108.073,77.506 108.977,78.41
  Top Layer w0.4: J2.2@22.629,82.263 22.987,82.621 v6(24.898,82.621) ; v14(105.511,75.204) 105.511,75.246 106.415,76.15 C53.1@106.415,76.175 106.615,76.375 106.615,77.243 R32.2@106.878,77.506
  Layer 3 w0.4: v6(24.898,82.621) 24.898,79.136 27.469,76.564 33.542,76.564 v7(33.58,76.526) 55.519,76.526 60.706,81.713 ; 74.823,81.713 60.706,81.713 ; 81.374,88.265 74.822,81.713 60.706,81.713 ; 81.375,88.265 95.198,88.265 96.475,86.988 96.475,83.448 104.631,75.292 104.841,75.292 104.872,75.261 105.454,75.261 v14(105.511,75.204)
